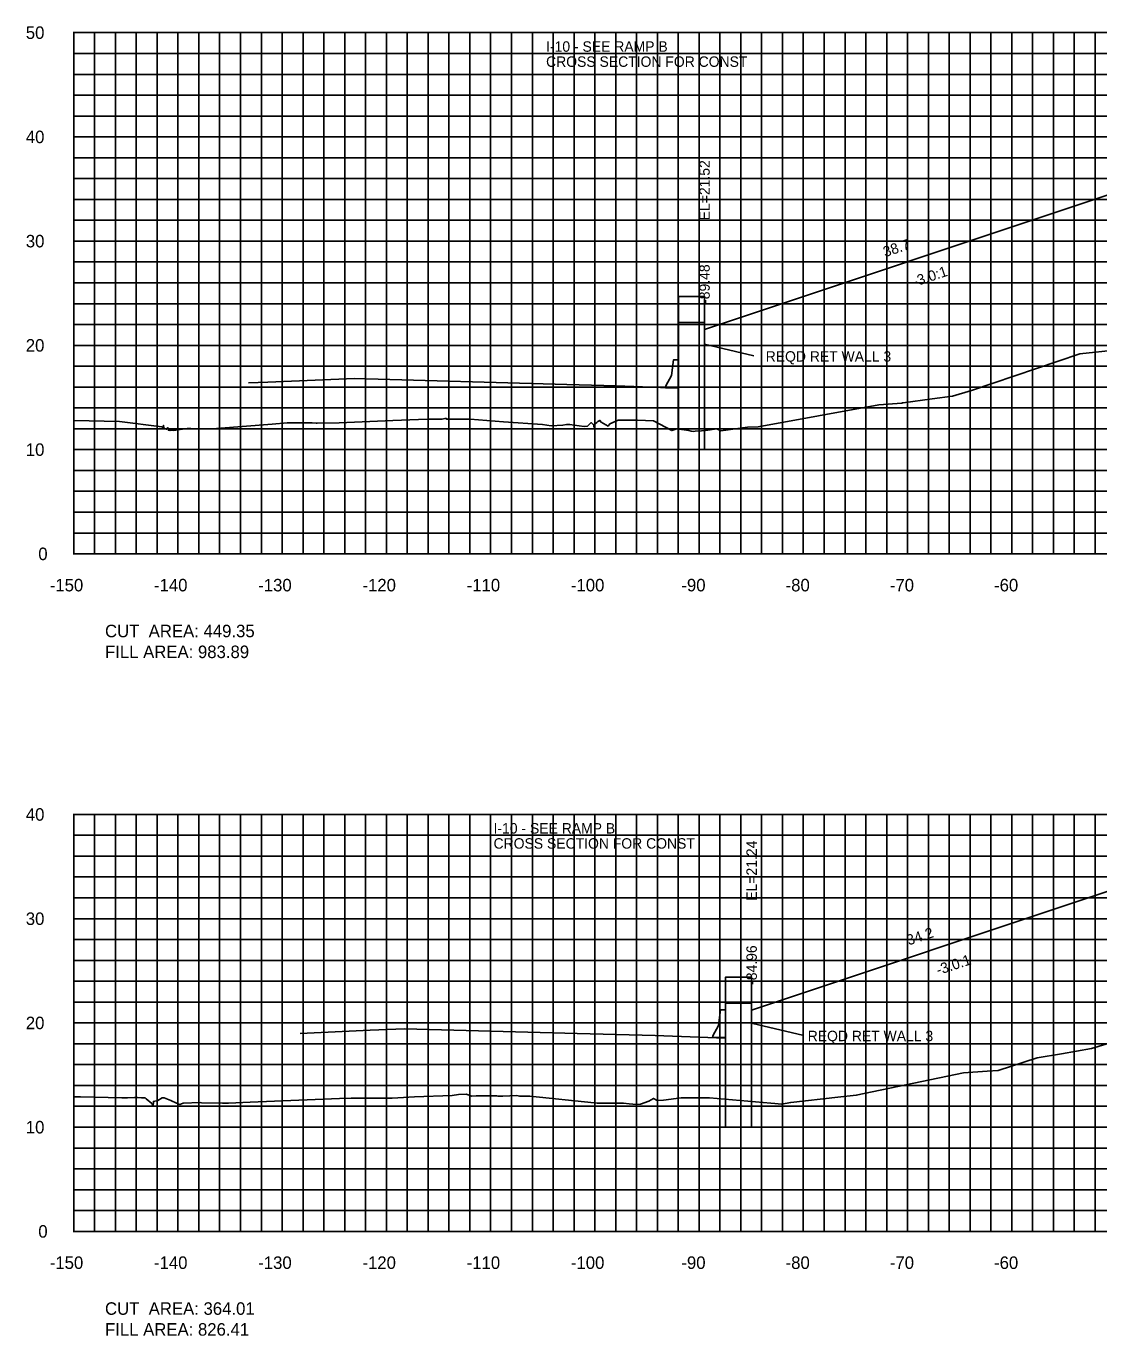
# Model space of a CAD drawing. Extents: x 1800880 to 1818864, y 245271 to 250560.
# Drawn here: x 1808256.4 to 1808359.4, y 250089.4 to 250215 of the extents above; entities that cross this region are included whole.
import ezdxf

# ---------------------------------------------------------------- set-up
doc = ezdxf.new("R2010")
doc.units = 0
for name, color, linetype in [('33', 7, 'Continuous'), ('ANNO-TXT', 7, 'Continuous'), ('CL-CNST', 7, 'Continuous'), ('Default', 7, 'Continuous'), ('DESIGN - DRAINAGE - Bridges', 7, 'Continuous'), ('DRAINAGETXT', 7, 'Continuous'), ('EPTEXT', 7, 'Continuous'), ('Level 37', 7, 'Continuous'), ('Level 46', 7, 'Continuous'), ('Level 62', 7, 'Continuous'), ('SHT-BDR', 7, 'Continuous')]:
    doc.layers.add(name, color=color, linetype=linetype)

msp = doc.modelspace()

# ---------------------------------------------------------------- linework, layer by layer
at = {"layer": 'CL-CNST'}
for points in [[(1808261, 250177.21), (1808265.39, 250177.13), (1808269.46, 250176.6), (1808269.6, 250176.52), (1808269.61, 250176.77), (1808269.64, 250176.5), (1808269.64, 250176.54), (1808269.67, 250176.5), (1808269.71, 250176.44), (1808269.73, 250176.42), (1808269.78, 250176.43), (1808269.84, 250176.42), (1808269.89, 250176.4), (1808269.93, 250176.38), (1808270.04, 250176.55), (1808270.09, 250176.28), (1808270.13, 250176.32), (1808270.14, 250176.32), (1808270.15, 250176.27), (1808270.17, 250176.28), (1808270.25, 250176.25), (1808270.43, 250176.28), (1808270.57, 250176.27), (1808271.67, 250176.43), (1808271.89, 250176.47), (1808272, 250176.45), (1808272.22, 250176.44), (1808272.42, 250176.42), (1808273.38, 250176.43), (1808274.69, 250176.44), (1808280.03, 250176.88), (1808281.49, 250176.99), (1808281.82, 250177), (1808283.86, 250177), (1808284.25, 250176.96), (1808284.27, 250176.96), (1808284.36, 250176.96), (1808286.45, 250176.99), (1808291.62, 250177.22), (1808294.07, 250177.33), (1808295.08, 250177.35), (1808296.36, 250177.36), (1808296.61, 250177.43), (1808296.76, 250177.43), (1808296.79, 250177.34), (1808297.6, 250177.34), (1808299.03, 250177.34), (1808302.24, 250177.11), (1808305.96, 250176.84), (1808306.81, 250176.72), (1808307.93, 250176.78), (1808308.29, 250176.83), (1808308.6, 250176.83), (1808309.02, 250176.76), (1808309.96, 250176.64), (1808310.3, 250176.68), (1808310.66, 250177.03), (1808310.89, 250176.79), (1808310.89, 250176.6), (1808310.9, 250176.8), (1808310.92, 250176.84), (1808310.92, 250176.84), (1808311.19, 250177.04), (1808311.29, 250177.12), (1808311.49, 250177.23), (1808311.59, 250177.05), (1808312.26, 250176.68), (1808312.44, 250176.89), (1808313.24, 250177.24), (1808313.78, 250177.26), (1808315.09, 250177.26), (1808316.64, 250177.19), (1808318.37, 250176.26), (1808318.87, 250176.43), (1808320.01, 250176.26), (1808320.25, 250176.21), (1808320.46, 250176.18), (1808320.62, 250176.2), (1808321.22, 250176.24), (1808321.63, 250176.27), (1808322.69, 250176.42), (1808322.97, 250176.28), (1808323.07, 250176.24), (1808325.63, 250176.57), (1808326.67, 250176.63), (1808338.24, 250178.72), (1808340.45, 250178.89), (1808340.5, 250178.92), (1808340.57, 250178.93), (1808343.37, 250179.29), (1808345.32, 250179.55), (1808347.14, 250180.1), (1808357.54, 250183.62), (1808361.13, 250183.99)], [(1808261, 250112.34), (1808261.65, 250112.33), (1808265.61, 250112.26), (1808266.15, 250112.26), (1808266.17, 250112.24), (1808266.82, 250112.27), (1808267.05, 250112.27), (1808267.1, 250112.27), (1808267.11, 250112.27), (1808267.5, 250112.24), (1808267.64, 250112.26), (1808267.75, 250112.25), (1808267.84, 250112.24), (1808267.95, 250112.15), (1808268.48, 250111.69), (1808268.61, 250111.49), (1808268.64, 250111.9), (1808269.07, 250111.99), (1808269.47, 250112.26), (1808269.69, 250112.26), (1808270.33, 250111.98), (1808270.85, 250111.74), (1808271.18, 250111.62), (1808271.5, 250111.72), (1808273.14, 250111.79), (1808273.26, 250111.75), (1808275.28, 250111.74), (1808275.86, 250111.74), (1808277.92, 250111.83), (1808286.49, 250112.19), (1808287.62, 250112.21), (1808288.73, 250112.22), (1808289.03, 250112.22), (1808290.47, 250112.21), (1808291.55, 250112.2), (1808292.1, 250112.23), (1808293.68, 250112.35), (1808297.32, 250112.48), (1808297.91, 250112.57), (1808298.68, 250112.59), (1808298.74, 250112.58), (1808299.2, 250112.41), (1808299.61, 250112.45), (1808301.6, 250112.43), (1808301.72, 250112.4), (1808302.17, 250112.42), (1808303.5, 250112.47), (1808303.77, 250112.42), (1808304.26, 250112.4), (1808304.77, 250112.4), (1808310.92, 250111.78), (1808311.23, 250111.74), (1808311.43, 250111.74), (1808311.65, 250111.74), (1808312.25, 250111.74), (1808313.75, 250111.74), (1808314.29, 250111.68), (1808314.65, 250111.65), (1808315, 250111.6), (1808315.38, 250111.65), (1808316.19, 250111.94), (1808316.61, 250112.19), (1808316.99, 250112), (1808317.6, 250112.01), (1808319.27, 250112.23), (1808320.19, 250112.23), (1808320.89, 250112.23), (1808322, 250112.25), (1808327.89, 250111.72), (1808328.26, 250111.7), (1808328.92, 250111.64), (1808329.8, 250111.8), (1808334.31, 250112.3), (1808336.08, 250112.5), (1808346.36, 250114.64), (1808348.65, 250114.8), (1808349.71, 250114.87), (1808353.44, 250116.07), (1808355.78, 250116.48), (1808358.66, 250116.98), (1808364.9, 250118.86)]]:
    msp.add_lwpolyline(points, dxfattribs=at)
at = {"layer": 'Default'}
for p, q in [((1808319.03, 250180.37), (1808319.03, 250183.04)), ((1808323.54, 250118.02), (1808323.54, 250120.69))]:
    msp.add_line(p, q, dxfattribs=at)
for points in [[(1808319.03, 250183.04), (1808318.53, 250183.04), (1808318.35, 250181.54), (1808317.8, 250180.54), (1808317.78, 250180.37), (1808319.03, 250180.37)], [(1808323.54, 250120.69), (1808323.04, 250120.69), (1808322.86, 250119.19), (1808322.31, 250118.19), (1808322.29, 250118.02), (1808323.54, 250118.02)]]:
    msp.add_lwpolyline(points, dxfattribs=at)
at = {"layer": 'DESIGN - DRAINAGE - Bridges'}
for p, q in [((1808260.94, 250214.43), (1808261, 250214.43)), ((1808261, 250164.43), (1808261, 250214.43)), ((1808260.94, 250204.43), (1808261, 250204.43)), ((1808260.94, 250194.43), (1808261, 250194.43)), ((1808260.94, 250184.43), (1808261, 250184.43)), ((1808260.94, 250174.43), (1808261, 250174.43)), ((1808260.94, 250164.43), (1808261, 250164.43)), ((1808261, 250164.43), (1808561, 250164.43)), ((1808261, 250164.37), (1808261, 250164.43)), ((1808271, 250164.37), (1808271, 250164.43)), ((1808281, 250164.37), (1808281, 250164.43)), ((1808291, 250164.37), (1808291, 250164.43)), ((1808301, 250164.37), (1808301, 250164.43)), ((1808311, 250164.37), (1808311, 250164.43)), ((1808321, 250164.37), (1808321, 250164.43)), ((1808331, 250164.37), (1808331, 250164.43)), ((1808341, 250164.37), (1808341, 250164.43)), ((1808351, 250164.37), (1808351, 250164.43)), ((1808260.94, 250139.43), (1808261, 250139.43)), ((1808261, 250099.43), (1808261, 250139.43)), ((1808260.94, 250129.43), (1808261, 250129.43)), ((1808260.94, 250119.43), (1808261, 250119.43)), ((1808260.94, 250109.43), (1808261, 250109.43)), ((1808260.94, 250099.43), (1808261, 250099.43)), ((1808261, 250099.43), (1808561, 250099.43)), ((1808261, 250099.37), (1808261, 250099.43)), ((1808271, 250099.37), (1808271, 250099.43)), ((1808281, 250099.37), (1808281, 250099.43)), ((1808291, 250099.37), (1808291, 250099.43)), ((1808301, 250099.37), (1808301, 250099.43)), ((1808311, 250099.37), (1808311, 250099.43)), ((1808321, 250099.37), (1808321, 250099.43)), ((1808331, 250099.37), (1808331, 250099.43)), ((1808341, 250099.37), (1808341, 250099.43)), ((1808351, 250099.37), (1808351, 250099.43))]:
    msp.add_line(p, q, dxfattribs=at)
at = {"layer": 'EPTEXT'}
for p, q in [((1808326.25, 250183.43), (1808321.53, 250184.53)), ((1808331.04, 250118.23), (1808326.04, 250119.4))]:
    msp.add_line(p, q, dxfattribs=at)
at = {"layer": 'Level 37'}
for p, q in [((1808321.52, 250185.96), (1808321.52, 250187.96)), ((1808326.04, 250120.67), (1808326.04, 250122.67))]:
    msp.add_line(p, q, dxfattribs=at)
at = {"layer": 'Level 46'}
for p, q in [((1808261, 250214.43), (1808561, 250214.43)), ((1808261, 250164.43), (1808261, 250214.43)), ((1808263, 250164.43), (1808263, 250214.43)), ((1808265, 250164.43), (1808265, 250214.43)), ((1808267, 250164.43), (1808267, 250214.43)), ((1808269, 250164.43), (1808269, 250214.43)), ((1808271, 250164.43), (1808271, 250214.43)), ((1808273, 250164.43), (1808273, 250214.43)), ((1808275, 250164.43), (1808275, 250214.43)), ((1808277, 250164.43), (1808277, 250214.43)), ((1808279, 250164.43), (1808279, 250214.43)), ((1808281, 250164.43), (1808281, 250214.43)), ((1808283, 250164.43), (1808283, 250214.43)), ((1808285, 250164.43), (1808285, 250214.43)), ((1808287, 250164.43), (1808287, 250214.43)), ((1808289, 250164.43), (1808289, 250214.43)), ((1808291, 250164.43), (1808291, 250214.43)), ((1808293, 250164.43), (1808293, 250214.43)), ((1808295, 250164.43), (1808295, 250214.43)), ((1808297, 250164.43), (1808297, 250214.43)), ((1808299, 250164.43), (1808299, 250214.43)), ((1808301, 250164.43), (1808301, 250214.43)), ((1808303, 250164.43), (1808303, 250214.43)), ((1808305, 250164.43), (1808305, 250214.43)), ((1808307, 250164.43), (1808307, 250214.43)), ((1808309, 250164.43), (1808309, 250214.43)), ((1808311, 250164.43), (1808311, 250214.43)), ((1808313, 250164.43), (1808313, 250214.43)), ((1808315, 250164.43), (1808315, 250214.43)), ((1808317, 250164.43), (1808317, 250214.43)), ((1808319, 250164.43), (1808319, 250214.43)), ((1808321, 250164.43), (1808321, 250214.43)), ((1808323, 250164.43), (1808323, 250214.43)), ((1808325, 250164.43), (1808325, 250214.43)), ((1808327, 250164.43), (1808327, 250214.43)), ((1808329, 250164.43), (1808329, 250214.43)), ((1808331, 250164.43), (1808331, 250214.43)), ((1808333, 250164.43), (1808333, 250214.43)), ((1808335, 250164.43), (1808335, 250214.43)), ((1808337, 250164.43), (1808337, 250214.43)), ((1808339, 250164.43), (1808339, 250214.43)), ((1808341, 250164.43), (1808341, 250214.43)), ((1808343, 250164.43), (1808343, 250214.43)), ((1808345, 250164.43), (1808345, 250214.43)), ((1808347, 250164.43), (1808347, 250214.43)), ((1808349, 250164.43), (1808349, 250214.43)), ((1808351, 250164.43), (1808351, 250214.43)), ((1808353, 250164.43), (1808353, 250214.43)), ((1808355, 250164.43), (1808355, 250214.43)), ((1808357, 250164.43), (1808357, 250214.43)), ((1808359, 250164.43), (1808359, 250214.43)), ((1808261, 250212.43), (1808561, 250212.43)), ((1808261, 250210.43), (1808561, 250210.43)), ((1808261, 250208.43), (1808561, 250208.43)), ((1808261, 250206.43), (1808561, 250206.43)), ((1808261, 250204.43), (1808561, 250204.43)), ((1808261, 250202.43), (1808561, 250202.43)), ((1808261, 250200.43), (1808561, 250200.43)), ((1808261, 250198.43), (1808561, 250198.43)), ((1808261, 250196.43), (1808561, 250196.43)), ((1808261, 250194.43), (1808561, 250194.43)), ((1808261, 250192.43), (1808561, 250192.43)), ((1808261, 250190.43), (1808561, 250190.43)), ((1808261, 250188.43), (1808561, 250188.43)), ((1808261, 250186.43), (1808561, 250186.43)), ((1808261, 250184.43), (1808561, 250184.43)), ((1808261, 250182.43), (1808561, 250182.43)), ((1808261, 250180.43), (1808561, 250180.43)), ((1808261, 250178.43), (1808561, 250178.43)), ((1808261, 250176.43), (1808561, 250176.43)), ((1808261, 250174.43), (1808561, 250174.43)), ((1808261, 250172.43), (1808561, 250172.43)), ((1808261, 250170.43), (1808561, 250170.43)), ((1808261, 250168.43), (1808561, 250168.43)), ((1808261, 250166.43), (1808561, 250166.43)), ((1808261, 250164.43), (1808561, 250164.43)), ((1808261, 250139.43), (1808561, 250139.43)), ((1808261, 250099.43), (1808261, 250139.43)), ((1808263, 250099.43), (1808263, 250139.43)), ((1808265, 250099.43), (1808265, 250139.43)), ((1808267, 250099.43), (1808267, 250139.43)), ((1808269, 250099.43), (1808269, 250139.43)), ((1808271, 250099.43), (1808271, 250139.43)), ((1808273, 250099.43), (1808273, 250139.43)), ((1808275, 250099.43), (1808275, 250139.43)), ((1808277, 250099.43), (1808277, 250139.43)), ((1808279, 250099.43), (1808279, 250139.43)), ((1808281, 250099.43), (1808281, 250139.43)), ((1808283, 250099.43), (1808283, 250139.43)), ((1808285, 250099.43), (1808285, 250139.43)), ((1808287, 250099.43), (1808287, 250139.43)), ((1808289, 250099.43), (1808289, 250139.43)), ((1808291, 250099.43), (1808291, 250139.43)), ((1808293, 250099.43), (1808293, 250139.43)), ((1808295, 250099.43), (1808295, 250139.43)), ((1808297, 250099.43), (1808297, 250139.43)), ((1808299, 250099.43), (1808299, 250139.43)), ((1808301, 250099.43), (1808301, 250139.43)), ((1808303, 250099.43), (1808303, 250139.43)), ((1808305, 250099.43), (1808305, 250139.43)), ((1808307, 250099.43), (1808307, 250139.43)), ((1808309, 250099.43), (1808309, 250139.43)), ((1808311, 250099.43), (1808311, 250139.43)), ((1808313, 250099.43), (1808313, 250139.43)), ((1808315, 250099.43), (1808315, 250139.43)), ((1808317, 250099.43), (1808317, 250139.43)), ((1808319, 250099.43), (1808319, 250139.43)), ((1808321, 250099.43), (1808321, 250139.43)), ((1808323, 250099.43), (1808323, 250139.43)), ((1808325, 250099.43), (1808325, 250139.43)), ((1808327, 250099.43), (1808327, 250139.43)), ((1808329, 250099.43), (1808329, 250139.43)), ((1808331, 250099.43), (1808331, 250139.43)), ((1808333, 250099.43), (1808333, 250139.43)), ((1808335, 250099.43), (1808335, 250139.43)), ((1808337, 250099.43), (1808337, 250139.43)), ((1808339, 250099.43), (1808339, 250139.43)), ((1808341, 250099.43), (1808341, 250139.43)), ((1808343, 250099.43), (1808343, 250139.43)), ((1808345, 250099.43), (1808345, 250139.43)), ((1808347, 250099.43), (1808347, 250139.43)), ((1808349, 250099.43), (1808349, 250139.43)), ((1808351, 250099.43), (1808351, 250139.43)), ((1808353, 250099.43), (1808353, 250139.43)), ((1808355, 250099.43), (1808355, 250139.43)), ((1808357, 250099.43), (1808357, 250139.43)), ((1808359, 250099.43), (1808359, 250139.43)), ((1808261, 250137.43), (1808561, 250137.43)), ((1808261, 250135.43), (1808561, 250135.43)), ((1808261, 250133.43), (1808561, 250133.43)), ((1808261, 250131.43), (1808561, 250131.43)), ((1808261, 250129.43), (1808561, 250129.43)), ((1808261, 250127.43), (1808561, 250127.43)), ((1808261, 250125.43), (1808561, 250125.43)), ((1808261, 250123.43), (1808561, 250123.43)), ((1808261, 250121.43), (1808561, 250121.43)), ((1808261, 250119.43), (1808561, 250119.43)), ((1808261, 250117.43), (1808561, 250117.43)), ((1808261, 250115.43), (1808561, 250115.43)), ((1808261, 250113.43), (1808561, 250113.43)), ((1808261, 250111.43), (1808561, 250111.43)), ((1808261, 250109.43), (1808561, 250109.43)), ((1808261, 250107.43), (1808561, 250107.43)), ((1808261, 250105.43), (1808561, 250105.43)), ((1808261, 250103.43), (1808561, 250103.43)), ((1808261, 250101.43), (1808561, 250101.43)), ((1808261, 250099.43), (1808561, 250099.43))]:
    msp.add_line(p, q, dxfattribs=at)
at = {"layer": 'Level 62'}
for points in [[(1808321.52, 250185.96), (1808360.25, 250198.87), (1808363.75, 250199.01), (1808365.75, 250199.09), (1808374.68, 250199.44), (1808374.75, 250199.52), (1808375.75, 250199.56), (1808387.75, 250199.82), (1808399.75, 250199.56), (1808409.75, 250199.16), (1808412.25, 250198.97), (1808426.88, 250199.56), (1808438.88, 250199.82), (1808443.5, 250199.72), (1808455.51, 250199.45), (1808456.5, 250199.41), (1808456.58, 250199.34), (1808465.51, 250198.98), (1808467.51, 250198.9), (1808471.01, 250198.76), (1808524.66, 250180.88), (1808529.16, 250180.88)], [(1808277.76, 250180.83), (1808279.61, 250180.9), (1808287.94, 250181.25), (1808308.32, 250180.68), (1808313.05, 250180.55), (1808318.14, 250180.36), (1808319.03, 250180.32)], [(1808326.04, 250120.67), (1808360.25, 250132.08), (1808363.75, 250132.22), (1808365.75, 250132.3), (1808374.68, 250132.65), (1808374.75, 250132.73), (1808375.75, 250132.77), (1808387.75, 250132.81), (1808399.75, 250132.54), (1808409.75, 250132.14), (1808412.25, 250132.13), (1808428.1, 250132.77), (1808440.1, 250132.81), (1808445.94, 250132.68), (1808457.94, 250132.41), (1808458.94, 250132.37), (1808459.01, 250132.3), (1808467.94, 250131.94), (1808469.94, 250131.86), (1808473.45, 250131.72), (1808518.28, 250116.78), (1808522.78, 250116.78)], [(1808282.72, 250118.43), (1808289.45, 250118.72), (1808292.74, 250118.86), (1808309.3, 250118.43), (1808316.79, 250118.22), (1808320.97, 250118.07), (1808323.54, 250117.97)]]:
    msp.add_lwpolyline(points, dxfattribs=at)
for points in [[(1808321.53, 250186.62), (1808319.03, 250186.62), (1808319.03, 250189.12), (1808321.53, 250189.12)], [(1808319.03, 250174.43), (1808321.53, 250174.43), (1808321.53, 250186.62), (1808319.03, 250186.62)], [(1808326.04, 250121.33), (1808323.54, 250121.33), (1808323.54, 250123.83), (1808326.04, 250123.83)], [(1808323.54, 250109.43), (1808326.04, 250109.43), (1808326.04, 250121.33), (1808323.54, 250121.33)]]:
    msp.add_lwpolyline(points, close=True, dxfattribs=at)

# ---------------------------------------------------------------- texts
for s, p in [('-150', (1808258.7, 250160.83)), ('-140', (1808268.7, 250160.83)), ('-130', (1808278.7, 250160.83)), ('-120', (1808288.7, 250160.83)), ('-110', (1808298.7, 250160.83)), ('-100', (1808308.7, 250160.83)), ('-90', (1808319.3, 250160.83)), ('-80', (1808329.3, 250160.83)), ('-70', (1808339.3, 250160.83)), ('-60', (1808349.3, 250160.83)), ('-150', (1808258.7, 250095.83)), ('-140', (1808268.7, 250095.83)), ('-130', (1808278.7, 250095.83)), ('-120', (1808288.7, 250095.83)), ('-110', (1808298.7, 250095.83)), ('-100', (1808308.7, 250095.83)), ('-90', (1808319.3, 250095.83)), ('-80', (1808329.3, 250095.83)), ('-70', (1808339.3, 250095.83)), ('-60', (1808349.3, 250095.83))]:
    msp.add_text(s, height=1.2).set_placement(p)
at = {"layer": '33'}
for s, p in [('50', (1808256.4, 250213.83)), ('40', (1808256.4, 250203.83)), ('30', (1808256.4, 250193.83)), ('20', (1808256.4, 250183.83)), ('10', (1808256.4, 250173.83)), ('0', (1808257.6, 250163.83)), ('40', (1808256.4, 250138.83)), ('30', (1808256.4, 250128.83)), ('20', (1808256.4, 250118.83)), ('10', (1808256.4, 250108.83)), ('0', (1808257.6, 250098.83))]:
    msp.add_text(s, height=1.2, dxfattribs=at).set_placement(p)
at = {"layer": 'ANNO-TXT'}
for s, p in [('38.7', (1808338.85, 250192.89)), ('34.2', (1808341.11, 250126.86))]:
    msp.add_text(s, height=1, rotation=18.4348, dxfattribs=at).set_placement(p)
at = {"layer": 'DESIGN - DRAINAGE - Bridges'}
for p in [(1808261, 250164.43), (1808261, 250099.43)]:
    msp.add_text('-', height=0.0001, dxfattribs=at).set_placement(p)
at = {"layer": 'DRAINAGETXT'}
for s, p in [('CUT  AREA: 449.35', (1808264, 250156.43)), ('FILL AREA: 983.89', (1808264, 250154.43)), ('CUT  AREA: 364.01', (1808264, 250091.43)), ('FILL AREA: 826.41', (1808264, 250089.43))]:
    msp.add_text(s, height=1.2, dxfattribs=at).set_placement(p)
at = {"layer": 'EPTEXT'}
for s, p in [('I-10 - SEE RAMP B', (1808306.32, 250212.6)), ('CROSS SECTION FOR CONST ', (1808306.32, 250211.15)), ('REQD RET WALL 3', (1808327.39, 250182.87)), ('I-10 - SEE RAMP B', (1808301.28, 250137.6)), ('CROSS SECTION FOR CONST ', (1808301.28, 250136.15)), ('REQD RET WALL 3', (1808331.42, 250117.68))]:
    msp.add_text(s, height=1, dxfattribs=at).set_placement(p)
at = {"layer": 'Level 37'}
for p in [(1808341.68, 250190.04), (1808343.94, 250124)]:
    msp.add_text('-3.0:1', height=1, rotation=18.4348, dxfattribs=at).set_placement(p)
at = {"layer": 'SHT-BDR'}
for s, p in [('EL=21.52', (1808322.02, 250196.43)), ('-89.48', (1808322.02, 250188.41)), ('EL=21.24', (1808326.54, 250131.15)), ('-84.96', (1808326.54, 250123.08))]:
    msp.add_text(s, height=1, rotation=90, dxfattribs=at).set_placement(p)

doc.saveas('drawing.dxf')
